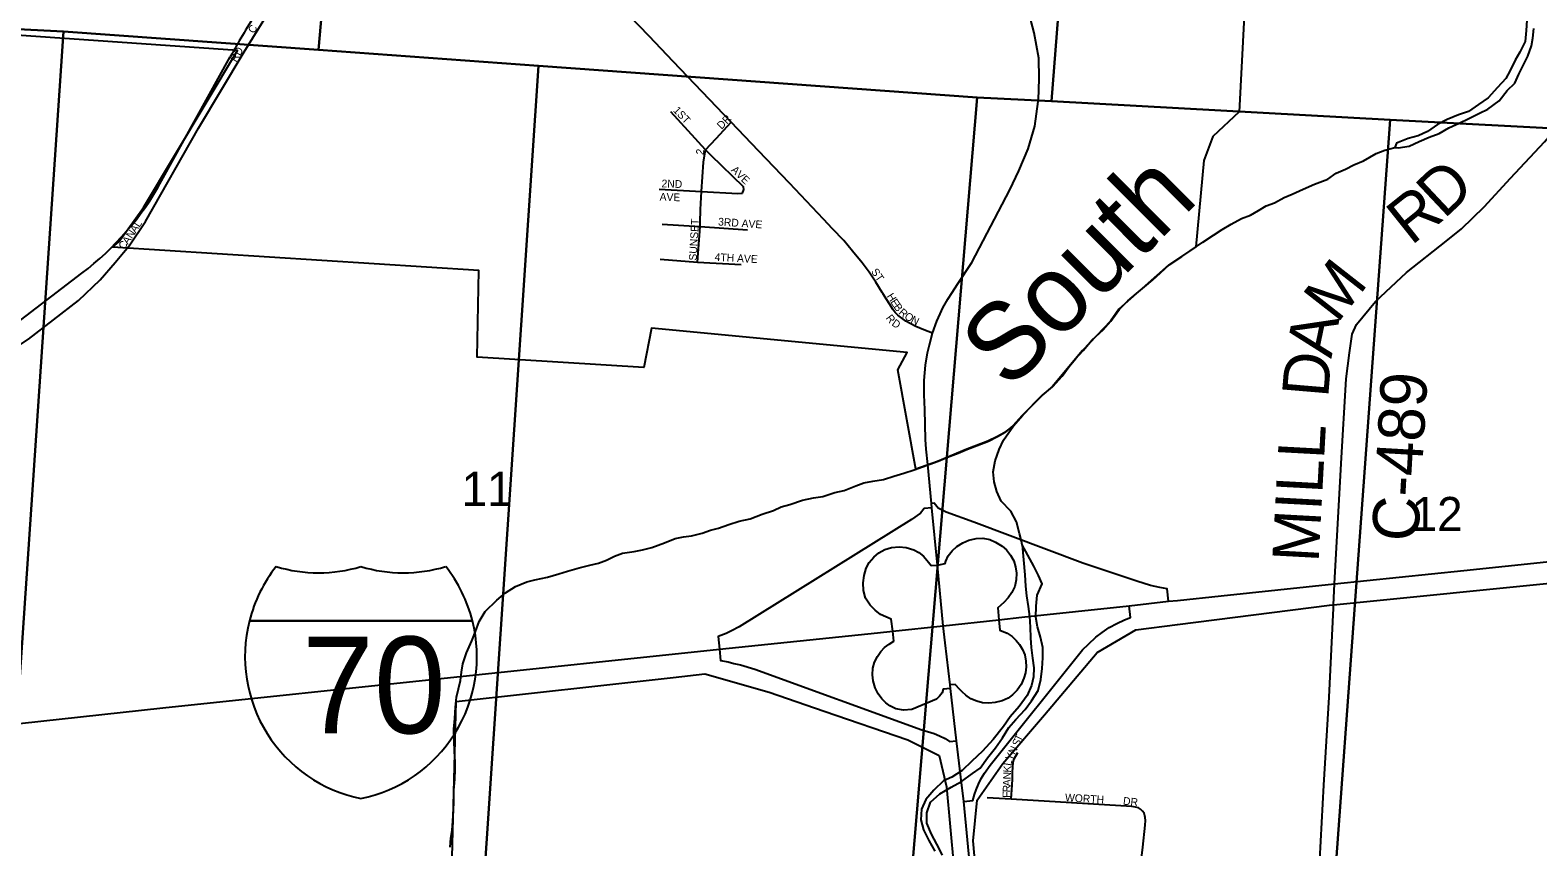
# Model space of a CAD drawing. Extents: x 0 to 40.4, y 0 to 22.
# Drawn here: x 6.04 to 7.886, y 15.73 to 16.73 of the extents above; entities that cross this region are included whole.
import ezdxf

# ---------------------------------------------------------------- set-up
doc = ezdxf.new("R2010")
doc.units = 0
for name, color, linetype in [('GM_X_City_Street', 7, 'Continuous'), ('GM_X_City_Street_Text', 7, 'Continuous'), ('GM_X_Corporation', 7, 'Continuous'), ('GM_X_County_Road', 7, 'Continuous'), ('GM_X_County_Road_Text', 7, 'Continuous'), ('GM_X_Interchange_Ramps', 7, 'Continuous'), ('GM_X_Interstate_Route', 7, 'Continuous'), ('GM_X_Interstate_Shield', 7, 'Continuous'), ('GM_X_Major_River', 7, 'Continuous'), ('GM_X_Major_River_Text', 7, 'Continuous'), ('GM_X_Section', 7, 'Continuous'), ('GM_X_Section_Text', 7, 'Continuous'), ('GM_X_State_Route', 7, 'Continuous'), ('GM_X_Township_Road', 7, 'Continuous'), ('SH_Data', 7, 'Continuous')]:
    doc.layers.add(name, color=color, linetype=linetype)

msp = doc.modelspace()

# ---------------------------------------------------------------- linework, layer by layer
at = {"layer": 'GM_X_City_Street'}
for points in [[(6.3019, 16.7029), (6.3302, 16.7491), (6.3505, 16.7865), (6.3929, 16.8555), (6.4592, 16.9443)], [(7.084, 16.4072), (7.0834, 16.4082), (7.0757, 16.421), (7.0673, 16.4332), (7.0588, 16.4445), (7.0469, 16.4591), (7.0362, 16.4719), (7.0225, 16.4863), (7.0113, 16.498), (6.9698, 16.5422), (6.9318, 16.5818), (6.8983, 16.6169), (6.8273, 16.6911), (6.7977, 16.7222), (6.7501, 16.772)], [(6.1538, 16.4573), (6.1609, 16.4656), (6.1808, 16.4952), (6.246, 16.6095), (6.3019, 16.7029)], [(6.8738, 16.5762), (6.8667, 16.5831), (6.8245, 16.6294)], [(6.8605, 16.494), (6.8609, 16.51), (6.8618, 16.5321), (6.8645, 16.5679), (6.8667, 16.5831), (6.8798, 16.5971), (6.8983, 16.6169)], [(6.9121, 16.5299), (6.914, 16.5345), (6.9134, 16.5377), (6.8738, 16.5762)], [(6.8102, 16.535), (6.8618, 16.5321), (6.9066, 16.5296), (6.9121, 16.5299)], [(6.8572, 16.4456), (6.8604, 16.4892), (6.8605, 16.494)], [(6.8138, 16.4921), (6.8604, 16.4892), (6.9184, 16.4851)], [(6.8113, 16.4492), (6.8572, 16.4456), (6.9106, 16.4428)], [(7.1451, 16.3584), (7.1342, 16.3625), (7.1247, 16.3667), (7.1174, 16.3704), (7.1121, 16.3732), (7.1073, 16.3769), (7.1023, 16.3808), (7.0994, 16.384), (7.0967, 16.3872), (7.084, 16.4072)], [(7.1916, 15.6998), (7.3976, 15.6894), (7.6176, 15.6748), (7.6181, 15.6909), (7.6244, 15.8052), (7.6307, 15.9128), (7.636, 16.0217)], [(7.2415, 15.7879), (7.2427, 15.8052), (7.243, 15.8131), (7.243, 15.8211), (7.2436, 15.8332), (7.2451, 15.8374), (7.2496, 15.8451)], [(7.3976, 15.6894), (7.4025, 15.7294), (7.4053, 15.7564), (7.406, 15.762), (7.4056, 15.7655), (7.4052, 15.7677), (7.4041, 15.7708), (7.4022, 15.7734), (7.3999, 15.776), (7.3972, 15.7775), (7.3938, 15.7783), (7.3893, 15.779), (7.2415, 15.7879), (7.2118, 15.7897)]]:
    msp.add_lwpolyline(points, dxfattribs=at)
at = {"layer": 'GM_X_Corporation'}
for points in [[(7.5619, 17.419), (7.5207, 16.6294), (7.4883, 16.5992), (7.4772, 16.5698), (7.4674, 16.4642), (7.4342, 16.4418), (7.3731, 16.3878), (7.3629, 16.3731), (7.3287, 16.3372), (7.2914, 16.293), (7.2789, 16.2824), (7.255, 16.2579), (7.2432, 16.245), (7.2334, 16.2371), (7.2239, 16.2318), (7.2129, 16.2262), (7.1871, 16.2164), (7.1512, 16.2014), (7.1245, 16.1919), (7.1023, 16.3135), (7.1138, 16.3351), (6.8006, 16.3649), (6.7914, 16.3166), (6.5873, 16.3294), (6.5891, 16.4355), (6.1406, 16.4637), (6.1481, 16.4704), (6.1784, 16.5123), (6.2938, 16.7046), (5.4873, 16.7605)], [(7.1978, 15.705), (7.1949, 15.7369), (7.1997, 15.7869), (7.2313, 15.8316), (7.2823, 15.8913), (7.3467, 15.9677), (7.3942, 15.9952), (7.445, 16.0017), (7.6312, 16.0254), (7.6362, 16.0259), (7.9257, 16.0548)], [(6.5553, 15.6693), (6.5616, 15.9075), (6.8274, 15.9372), (6.866, 15.9416), (6.9448, 15.9189), (7.0121, 15.8959), (7.1147, 15.8609), (7.1533, 15.8414), (7.1622, 15.803), (7.1709, 15.7051)]]:
    msp.add_lwpolyline(points, dxfattribs=at)
at = {"layer": 'GM_X_County_Road'}
msp.add_lwpolyline([(7.636, 16.0217), (7.6362, 16.0259), (7.6375, 16.0515), (7.6454, 16.1992), (7.6518, 16.3027), (7.6559, 16.3343), (7.6592, 16.3572), (7.6643, 16.369), (7.6877, 16.3975), (7.7254, 16.4327), (7.7742, 16.4712), (7.7928, 16.4863), (7.8207, 16.5131), (7.853, 16.5482), (7.8946, 16.593), (7.9628, 16.6727), (7.983, 16.6943), (7.9986, 16.7119)], dxfattribs=at)
at = {"layer": 'GM_X_Interchange_Ramps'}
for points in [[(7.1443, 16.1448), (7.1348, 16.1438), (7.1302, 16.1382), (7.1193, 16.1303), (6.908, 15.9989), (6.8988, 15.994), (6.8922, 15.9908), (6.8824, 15.9871), (6.8841, 15.9717)], [(7.4342, 16.0303), (7.4326, 16.0454), (7.4235, 16.0471), (7.4121, 16.0497), (7.3951, 16.0548), (7.3292, 16.0769), (7.1954, 16.1272), (7.1619, 16.1396), (7.152, 16.1445), (7.1468, 16.1505), (7.1437, 16.1501)], [(7.1512, 16.0745), (7.1604, 16.0766), (7.1612, 16.0793), (7.1643, 16.0859), (7.1689, 16.092), (7.1749, 16.0975), (7.182, 16.1018), (7.1893, 16.105), (7.1985, 16.1071), (7.2065, 16.1076), (7.215, 16.1058), (7.2223, 16.1028), (7.2305, 16.0978), (7.2355, 16.0935), (7.2405, 16.0867), (7.2444, 16.0798), (7.2466, 16.0724), (7.2478, 16.0649), (7.2473, 16.0564), (7.2457, 16.0486), (7.2421, 16.0409), (7.2376, 16.0345), (7.2323, 16.029), (7.2248, 16.0225), (7.2264, 16.0077)], [(7.0962, 15.9938), (7.0944, 16.0084), (7.0814, 16.0143), (7.0746, 16.0195), (7.0687, 16.0254), (7.0628, 16.0342), (7.0604, 16.0437), (7.06, 16.053), (7.0611, 16.0618), (7.0636, 16.0708), (7.0674, 16.0779), (7.0729, 16.0844), (7.0793, 16.0896), (7.0865, 16.0936), (7.0946, 16.0962), (7.1043, 16.0969), (7.1127, 16.0961), (7.1221, 16.0933), (7.1284, 16.0899), (7.1341, 16.0856), (7.1401, 16.0783), (7.1433, 16.074), (7.1512, 16.0745)], [(7.1833, 15.7851), (7.1942, 15.7863), (7.1964, 15.7938), (7.1986, 15.7996), (7.2013, 15.8065), (7.2047, 15.8132), (7.2088, 15.8199), (7.2154, 15.8297), (7.3286, 15.9707), (7.3361, 15.9779), (7.345, 15.9862), (7.3526, 15.9922), (7.3614, 15.9981), (7.3706, 16.0033), (7.3802, 16.0075), (7.3875, 16.0104), (7.3859, 16.0248)], [(7.1669, 15.9237), (7.1582, 15.9227), (7.1567, 15.9184), (7.1534, 15.9143), (7.15, 15.9105), (7.1198, 15.8977), (7.1094, 15.8969), (7.1002, 15.8987), (7.0925, 15.9023), (7.0879, 15.906), (7.0828, 15.911), (7.0783, 15.9171), (7.0747, 15.9244), (7.0724, 15.9328), (7.0715, 15.9404), (7.0717, 15.9484), (7.074, 15.9557), (7.0777, 15.9627), (7.0816, 15.9687), (7.0863, 15.9737), (7.0917, 15.9778), (7.0975, 15.9816), (7.0962, 15.9938)], [(7.2264, 16.0077), (7.2273, 15.9949), (7.2365, 15.9912), (7.2425, 15.9873), (7.2475, 15.9823), (7.2516, 15.9775), (7.2554, 15.9713), (7.2579, 15.9646), (7.2594, 15.9571), (7.2595, 15.9502), (7.2589, 15.9428), (7.2569, 15.936), (7.2536, 15.9283), (7.2487, 15.9215), (7.2431, 15.9156), (7.2376, 15.9119), (7.2304, 15.9083), (7.2218, 15.9066), (7.214, 15.9054), (7.2062, 15.906), (7.1994, 15.908), (7.1921, 15.911), (7.1857, 15.9152), (7.1814, 15.9196), (7.1786, 15.9224), (7.1726, 15.9286), (7.1664, 15.9279)], [(6.8841, 15.9717), (6.8852, 15.9579), (6.8948, 15.9562), (6.9016, 15.9543), (6.9097, 15.9524), (6.9273, 15.9474), (7.1319, 15.8729), (7.1471, 15.8684), (7.1536, 15.8656), (7.1606, 15.8625), (7.1659, 15.8586), (7.1743, 15.8595)]]:
    msp.add_lwpolyline(points, dxfattribs=at)
at = {"layer": 'GM_X_Interstate_Route'}
for points in [[(7.7959, 16.068), (7.8971, 16.0785), (8.0522, 16.0948), (8.1652, 16.1082), (8.2508, 16.1101), (8.3578, 16.109), (8.7001, 16.0907), (8.8023, 16.0849), (8.8184, 16.0837)], [(7.4984, 16.037), (7.6375, 16.0515), (7.7959, 16.068)], [(7.2545, 16.0107), (7.3859, 16.0248), (7.4342, 16.0303), (7.4449, 16.0314)], [(7.4449, 16.0314), (7.4984, 16.037)], [(7.0777, 15.9919), (7.0962, 15.9938), (7.158, 16.0002)], [(7.158, 16.0002), (7.2264, 16.0077), (7.2545, 16.0107)], [(4.2342, 15.8011), (4.3559, 15.795), (4.3687, 15.7943), (4.7616, 15.7706), (4.869, 15.7667), (5.0335, 15.7746), (5.2646, 15.7968), (5.5398, 15.8285), (5.6363, 15.8385), (6.0265, 15.8807), (6.202, 15.8998), (6.8841, 15.9717), (7.0777, 15.9919)]]:
    msp.add_lwpolyline(points, dxfattribs=at)
at = {"layer": 'GM_X_Interstate_Shield'}
for p, q in [((6.3082, 16.0063), (6.5815, 16.0063)), ((6.5815, 16.0063), (6.3082, 16.0063)), ((6.5815, 16.0063), (6.3082, 16.0063))]:
    msp.add_line(p, q, dxfattribs=at)
for centre, start, end in [((6.4804, 15.9628), 141.669, 165.8066), ((6.393, 16.2427), 253.0091, 286.9909), ((6.4967, 16.2427), 253.0091, 286.9909), ((6.4093, 15.9628), 14.1934, 38.331), ((6.4804, 15.9628), 165.8066, 258.463), ((6.4093, 15.9628), 281.537, 14.1934)]:
    msp.add_arc(centre, 0.1776, start, end, dxfattribs=at)
at = {"layer": 'GM_X_Major_River'}
for points in [[(7.873, 16.7418), (7.8722, 16.729), (7.871, 16.7157), (7.8645, 16.7028), (7.8588, 16.693), (7.8527, 16.6801), (7.8473, 16.6703), (7.8371, 16.6593), (7.8257, 16.6465), (7.8139, 16.6386), (7.8014, 16.6299), (7.7893, 16.6258), (7.7753, 16.6201), (7.7635, 16.6141), (7.7514, 16.6054), (7.7397, 16.6002), (7.7276, 16.5968), (7.7135, 16.5912), (7.7112, 16.5859)], [(7.7112, 16.5859), (7.7154, 16.5855), (7.729, 16.5877), (7.7411, 16.5933), (7.7533, 16.5986), (7.7654, 16.6031), (7.7775, 16.6099), (7.79, 16.6155), (7.8018, 16.6215), (7.815, 16.6279), (7.8253, 16.6328), (7.8389, 16.643), (7.8488, 16.6555), (7.8583, 16.6645), (7.8632, 16.6755), (7.8694, 16.688), (7.8743, 16.6979), (7.8789, 16.7103), (7.8804, 16.7198), (7.8816, 16.7316)], [(7.244, 16.2453), (7.2557, 16.2581), (7.2668, 16.2695), (7.2797, 16.2827), (7.2922, 16.2933), (7.3036, 16.3061), (7.3123, 16.3178), (7.3207, 16.3277), (7.3294, 16.3375), (7.3405, 16.3503), (7.3541, 16.3628), (7.3636, 16.3734), (7.3739, 16.3881), (7.3841, 16.3983), (7.3948, 16.407), (7.4046, 16.4153), (7.4149, 16.424), (7.4244, 16.4323), (7.435, 16.4421), (7.4502, 16.4523), (7.4604, 16.4594), (7.4759, 16.47), (7.4892, 16.4787), (7.4998, 16.4855), (7.5108, 16.4922), (7.5233, 16.499), (7.5343, 16.5031), (7.5442, 16.5088), (7.5536, 16.5144), (7.5639, 16.5182), (7.5756, 16.5246), (7.5855, 16.5287), (7.5991, 16.5347), (7.6127, 16.5408), (7.6294, 16.5471), (7.6393, 16.5543), (7.651, 16.5592), (7.6612, 16.5648), (7.673, 16.5697), (7.6885, 16.5784), (7.6991, 16.5825), (7.7112, 16.5859)], [(6.8729, 16.1174), (6.8827, 16.1197), (6.8956, 16.1242), (6.9081, 16.1283), (6.9217, 16.1313), (6.9365, 16.1369), (6.9501, 16.1414), (6.9596, 16.1459), (6.9702, 16.1489), (6.9857, 16.1542), (6.9993, 16.1568), (7.0107, 16.1586), (7.0254, 16.1635), (7.0368, 16.1661), (7.0512, 16.1717), (7.061, 16.1755), (7.072, 16.1773), (7.0849, 16.1796), (7.0974, 16.1837), (7.1099, 16.187), (7.1224, 16.1912), (7.1383, 16.1968), (7.1519, 16.2017), (7.1633, 16.2066), (7.1765, 16.2118), (7.1879, 16.2167), (7.1996, 16.2212), (7.2136, 16.2264), (7.2246, 16.2321), (7.2341, 16.2374), (7.244, 16.2453)], [(7.2547, 16.0993), (7.254, 16.1038), (7.2514, 16.1133), (7.2477, 16.1277), (7.2409, 16.1406), (7.2292, 16.1528), (7.2236, 16.1646), (7.2206, 16.1767), (7.2192, 16.1889), (7.2219, 16.2022), (7.2268, 16.2162), (7.2318, 16.2275), (7.244, 16.2453)], [(6.554, 15.7292), (6.5548, 15.7402), (6.5564, 15.7497), (6.5572, 15.7614), (6.5584, 15.7739), (6.5588, 15.7857), (6.5585, 15.799), (6.5597, 15.8126), (6.5601, 15.8244), (6.5601, 15.8339), (6.5594, 15.8464), (6.5588, 15.8737), (6.56, 15.8869), (6.5608, 15.9006), (6.562, 15.9131), (6.5643, 15.9233), (6.5666, 15.9332), (6.5681, 15.9434), (6.5697, 15.9536), (6.5743, 15.9673), (6.5808, 15.982), (6.585, 15.9934), (6.5896, 16.0055), (6.5972, 16.018), (6.6112, 16.0316), (6.6218, 16.0407), (6.634, 16.0486), (6.648, 16.0542), (6.6578, 16.0565), (6.6734, 16.0598), (6.6874, 16.0639), (6.698, 16.0673), (6.712, 16.0714), (6.7252, 16.0744), (6.7358, 16.077), (6.7457, 16.0808), (6.7555, 16.0857), (6.7654, 16.0894), (6.7794, 16.0912), (6.7896, 16.0935), (6.8013, 16.0961), (6.8168, 16.1017), (6.8297, 16.107), (6.8399, 16.1092), (6.8498, 16.1103), (6.863, 16.1137), (6.8729, 16.1174)], [(7.2547, 16.0993), (7.258, 16.0628), (7.2587, 16.0488), (7.2601, 16.037), (7.262, 16.0238), (7.2638, 16.0116), (7.2645, 15.9987), (7.2652, 15.9855), (7.2659, 15.9737), (7.2674, 15.9608), (7.2689, 15.949), (7.2688, 15.9377), (7.2661, 15.9271), (7.2608, 15.9149), (7.2513, 15.9017), (7.2399, 15.8889), (7.2319, 15.8771), (7.2193, 15.8612), (7.2064, 15.8469), (7.1931, 15.8344), (7.1814, 15.8231), (7.1685, 15.8148), (7.1586, 15.8107), (7.1465, 15.799), (7.1366, 15.7876), (7.1313, 15.7759), (7.1308, 15.7626), (7.1338, 15.7505), (7.1406, 15.7375), (7.1477, 15.7246)], [(7.1571, 15.7197), (7.1504, 15.733), (7.1436, 15.7451), (7.138, 15.7588), (7.1381, 15.7713), (7.1426, 15.7842), (7.154, 15.7944), (7.1677, 15.8027), (7.1806, 15.8098), (7.1938, 15.8193), (7.2033, 15.826), (7.2124, 15.8385), (7.2223, 15.851), (7.2307, 15.8631), (7.2383, 15.8756), (7.247, 15.8854), (7.2584, 15.8979), (7.2664, 15.9085), (7.2744, 15.9213), (7.2775, 15.9346), (7.2794, 15.9482), (7.2803, 15.9611), (7.2803, 15.9736), (7.2773, 15.9862), (7.2736, 15.9991), (7.2714, 16.0108), (7.2718, 16.0245), (7.273, 16.0378), (7.2791, 16.0518), (7.275, 16.062), (7.269, 16.0734), (7.2619, 16.0867), (7.2547, 16.0993)]]:
    msp.add_lwpolyline(points, dxfattribs=at)
at = {"layer": 'GM_X_Section'}
for points in [[(4.6284, 17.3961), (5.6266, 17.3411), (6.4444, 17.2982), (6.4106, 16.9046), (6.3929, 16.7053), (6.0805, 16.728), (5.57, 16.7542), (5.0349, 16.7787), (4.5943, 16.8006)], [(6.4444, 17.2982), (6.915, 17.2679), (7.3378, 17.2417), (7.2909, 16.6427), (7.1996, 16.6471), (6.6625, 16.6858), (6.3929, 16.7053), (6.4106, 16.9046)], [(7.3378, 17.2417), (7.7228, 17.2207), (8.2373, 17.1912), (8.202, 16.6562), (8.1953, 16.5941), (7.7054, 16.6198), (7.2909, 16.6427)], [(6.0805, 16.728), (6.012, 15.7142), (5.5033, 15.7422), (5.57, 16.7542)], [(6.0805, 16.728), (6.3929, 16.7053), (6.6625, 16.6858), (6.5945, 15.6728), (6.012, 15.7142)], [(6.6625, 16.6858), (7.1996, 16.6471), (7.1143, 15.6359), (6.5945, 15.6728)], [(7.1996, 16.6471), (7.2909, 16.6427), (7.7054, 16.6198), (7.6314, 15.5996), (7.1143, 15.6359)], [(7.7054, 16.6198), (8.1953, 16.5941), (8.1289, 15.6484), (8.124, 15.5684), (7.6314, 15.5996)]]:
    msp.add_lwpolyline(points, close=True, dxfattribs=at)
at = {"layer": 'GM_X_State_Route'}
for points in [[(7.2747, 16.6438), (7.2755, 16.6702), (7.2751, 16.6952), (7.2696, 16.7262), (7.2587, 16.7671), (7.2113, 16.9201), (7.2077, 16.9333), (7.1476, 17.1281)], [(7.1451, 16.3584), (7.1503, 16.3732), (7.1543, 16.3821), (7.1578, 16.3895), (7.1639, 16.4004), (7.169, 16.4084), (7.1755, 16.4185), (7.193, 16.445), (7.2396, 16.5341), (7.2509, 16.5573), (7.2623, 16.5841), (7.2705, 16.6119), (7.2746, 16.6424), (7.2747, 16.6438)], [(7.1374, 16.2166), (7.1363, 16.2284), (7.1357, 16.2651), (7.1346, 16.2832), (7.1349, 16.3005), (7.1365, 16.3193), (7.139, 16.3343), (7.1413, 16.3444), (7.1451, 16.3584)], [(7.1392, 16.1976), (7.1374, 16.2166)], [(7.1604, 15.9796), (7.158, 16.0002), (7.1512, 16.0745), (7.1443, 16.1448), (7.1437, 16.1501), (7.1392, 16.1976)], [(7.1797, 15.8149), (7.1743, 15.8595), (7.1669, 15.9237), (7.1664, 15.9279), (7.1604, 15.9796)], [(7.1916, 15.6998), (7.1833, 15.7851), (7.1797, 15.8149)]]:
    msp.add_lwpolyline(points, dxfattribs=at)
at = {"layer": 'GM_X_Township_Road'}
msp.add_lwpolyline([(5.4141, 15.9936), (5.4172, 15.9969), (5.4433, 16.0234), (5.4557, 16.0306), (5.4851, 16.0498), (5.506, 16.063), (5.5346, 16.078), (5.5689, 16.0961), (5.6016, 16.1112), (5.6389, 16.1292), (5.6888, 16.1506), (5.7768, 16.1829), (5.7867, 16.187), (5.7962, 16.1919), (5.8042, 16.1968), (5.8133, 16.2021), (6.0375, 16.3514), (6.0989, 16.3986), (6.1252, 16.4239), (6.1436, 16.4453), (6.1538, 16.4573)], dxfattribs=at)
at = {"layer": 'SH_Data'}
for p, q in [((6.2007, 16.5449), (6.2847, 16.6969)), ((5.8805, 16.2624), (6.1031, 16.4319))]:
    msp.add_line(p, q, dxfattribs=at)
for centre, radius, start, end in [((7.2338, 16.1726), 1.0843, 147.8861, 151.0868), ((5.8841, 16.7198), 0.3617, 307.2699, 331.0868)]:
    msp.add_arc(centre, radius, start, end, dxfattribs=at)

# ---------------------------------------------------------------- texts
at = {"layer": 'GM_X_City_Street_Text'}
for s, rotation, p in [('C', 59.0654, (6.3138, 16.7247)), ('RD', 59.5418, (6.2921, 16.6896)), ('1ST', 313.2651, (6.8266, 16.6308)), ('DR', 45, (6.8865, 16.6075)), ('2', 81.8743, (6.8644, 16.5765)), ('AVE', 316.3964, (6.8974, 16.5575)), ('AVE', 358.0264, (6.8106, 16.5209)), ('2ND', 357.8801, (6.8129, 16.5372)), ('L', 56.7344, (6.1735, 16.4874)), ('SUNSET', 86.7001, (6.856, 16.4472)), ('3RD AVE', 356.0531, (6.8821, 16.4905)), ('A', 55.1289, (6.1594, 16.4664)), ('N', 56.7124, (6.1643, 16.4735)), ('A', 56.7278, (6.1689, 16.4805)), ('C', 49.9177, (6.154, 16.46)), ('4TH AVE', 356.9352, (6.8779, 16.4472)), ('ST', 304.6908, (7.0693, 16.4339)), ('H', 302.441, (7.0885, 16.4039)), ('E', 302.4434, (7.0929, 16.3968)), ('R', 307.0399, (7.0873, 16.377)), ('B', 304.7537, (7.0968, 16.3909)), ('R', 318.851, (7.1027, 16.3828)), ('O', 327.8631, (7.1097, 16.3769)), ('D', 325.5843, (7.0942, 16.3687)), ('N', 332.6391, (7.1175, 16.372)), ('T', 64.0931, (7.2533, 15.8577)), ('N', 64.1974, (7.2457, 15.842)), ('S', 64.0703, (7.2504, 15.8517)), ('K', 86.3255, (7.241, 15.8204)), ('L', 80.9734, (7.2415, 15.8284)), ('Y', 66.4369, (7.2424, 15.8344)), ('A', 88.404, (7.2406, 15.8038)), ('N', 88.404, (7.2408, 15.8121)), ('F', 88.4149, (7.2402, 15.7896)), ('R', 88.3967, (7.2404, 15.7963)), ('WORTH', 356.631, (7.3071, 15.7855)), ('DR', 353.9946, (7.378, 15.7814))]:
    msp.add_text(s, height=0.00947, rotation=rotation, dxfattribs=at).set_placement(p)
at = {"layer": 'GM_X_County_Road_Text'}
for s, height, rotation, p in [('D', 0.0568, 43.2396, (7.7715, 16.4975)), ('R', 0.0568, 38.6031, (7.7313, 16.4651)), ('M', 0.0568, 51.974, (7.6407, 16.3695)), ('A', 0.0568, 78.2243, (7.6334, 16.3268)), ('D', 0.0568, 85.1677, (7.6295, 16.2787)), ('C-489', 0.05682, 86.7298, (7.7397, 16.1025)), ('MILL', 0.05682, 86.913, (7.6178, 16.0772))]:
    msp.add_text(s, height=height, rotation=rotation, dxfattribs=at).set_placement(p)
at = {"layer": 'GM_X_Interstate_Shield'}
msp.add_text('70', height=0.11837, dxfattribs=at).set_placement((6.3726, 15.8687))
at = {"layer": 'GM_X_Major_River_Text'}
msp.add_text('South', height=0.0947, rotation=45.0029, dxfattribs=at).set_placement((7.2386, 16.287))
at = {"layer": 'GM_X_Section_Text'}
for s, p in [('11', (6.5682, 16.1471)), ('12', (7.732, 16.1162))]:
    msp.add_text(s, height=0.04186, rotation=0, dxfattribs=at).set_placement(p)

doc.saveas('drawing.dxf')
